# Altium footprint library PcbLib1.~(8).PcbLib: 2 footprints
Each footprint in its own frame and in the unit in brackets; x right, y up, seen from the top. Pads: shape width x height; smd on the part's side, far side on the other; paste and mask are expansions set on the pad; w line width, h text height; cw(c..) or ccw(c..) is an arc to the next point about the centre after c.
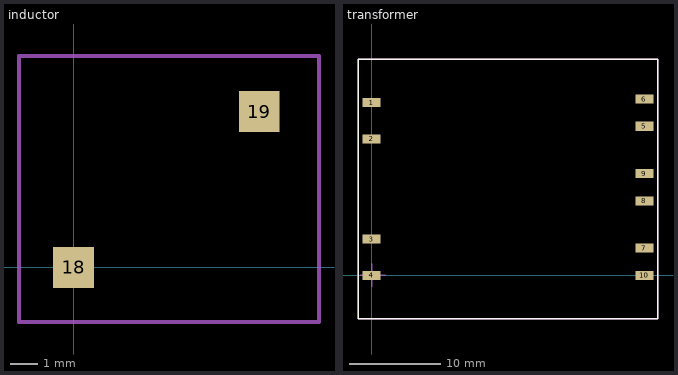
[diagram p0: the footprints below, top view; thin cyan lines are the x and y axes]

## inductor [mm]
pads (2):
  rect 1.5x1.5 smd: 18(0,0) 19(6.808,5.71)
Top Assembly:
  lines w0.15: -2,-2 9,-2 9,7.75 -2,7.75 -2,-2

## transformer [mm]
pads (10):
  rect 2x1 smd: 1(0,19) 2(0,15) 3(0,4) 4(0,0) 5(30,16.4) 6(30,19.4) 7(30,3) 8(30,8.2) 9(30,11.2) 10(30,0)
Top Overlay:
  lines w0.15: -1.5,-4.8 31.5,-4.8 31.5,23.8 -1.5,23.8 -1.5,-4.8
Top Assembly:
  lines w0.15: -1.5,-4.8 -1.5,23.8 31.5,23.8 31.5,-4.8 -1.5,-4.8
Top Courtyard:
  lines w0.15: -1.5,-4.8 31.5,-4.8 31.5,23.8 -1.5,23.8 -1.5,-4.8
Top Component Center:
  lines w0.15: -1.25,0 1.5,0 ; 0,-1.25 0,1.25
3D body "64.stp": height 17.75, standoff 0, extent -1,-4.8 31,23.8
